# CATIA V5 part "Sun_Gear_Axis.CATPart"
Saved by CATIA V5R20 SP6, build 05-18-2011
Part number: Sun_Gear_Axis
Bounding box of the stored display mesh (mm): x 0 to 10, y -2.499 to 2.499, z -2.499 to 2.499
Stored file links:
  E:\#01 CATIA Lecture Materials\#06 DMU\#16 DMU Page01 KIN EX16\Sun_Gear_Axis.CATPart
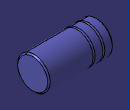
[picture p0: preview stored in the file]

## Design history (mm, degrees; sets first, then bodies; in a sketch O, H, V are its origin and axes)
Set1
  Point1: (0, 0, 0)
Body1 (main body)
  Sketch1 on zx-plane, origin (0, 0, 0), H (-1, 0, 0), V (0, 0, 1)
    axis line L1 (0, 0) -> (-10, 0)
    line L2 (0, 0) -> (0, 2.5)
    line L3 (0, 2.5) -> (-1.35, 2.5)
    line L4 (-10, 2.5) -> (-10, 0)
    arc A1 centre (-3, 2.5) radius 0.15 from (-3.15, 2.5) to (-2.85, 2.5) ccw
    point P4 (-3, 2.5)
    arc A2 centre (-1.5, 2.5) radius 0.15 from (-1.65, 2.5) to (-1.35, 2.5) ccw
    point P5 (-1.5, 2.5)
    point P6 (-2.85, 2.5)
    line L5 (-3.15, 2.5) -> (-10, 2.5)
    point P7 (-3.15, 2.5)
    point P8 (-1.35, 2.5)
    line L6 (-1.65, 2.5) -> (-2.85, 2.5)
    point P9 (-1.65, 2.5)
    point P10 (-1.65, 2.5)
    point P11 (-1.35, 2.5)
    point P12 (-3.15, 2.5)
    point P13 (-2.85, 2.5)
    distance L3 H = 2.5
    distance L4 L2 = 10
    radius A1 = 0.15
    radius A2 = 0.15
    distance L2 P5 = 1.5
    distance P5 P4 = 1.5
    horizontal: L1 H, L3 H, L5 H, L6 H
    vertical: L2 V, L4 V
    coincidence: P4 L3, P5 L3, A1 P6, A1 P7, L3 L5, A2 P8, A2 P9, L3 L6, L3 P11, L6 P10, L6 P13, L5 P12, P6 P13, P7 P12, P8 P11, P9 P10
  Shaft1: profile Sketch1, axis Sketch1.L1, angle 360
  Chamfer1: length 0.2, angle 45, on face of Shaft1 from Sketch1.L4; face of Shaft1 from Sketch1.L2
